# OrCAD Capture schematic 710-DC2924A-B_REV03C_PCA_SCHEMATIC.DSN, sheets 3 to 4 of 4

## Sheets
3 PAGE2: size Custom; title: DSP6713 SYSTEM; rev: V1.0; company: WITH DIGITAL POWER MANAGEMENT; note: 4 X 30A STEP-DOWN µMODULE SUPPLY WITH PSM
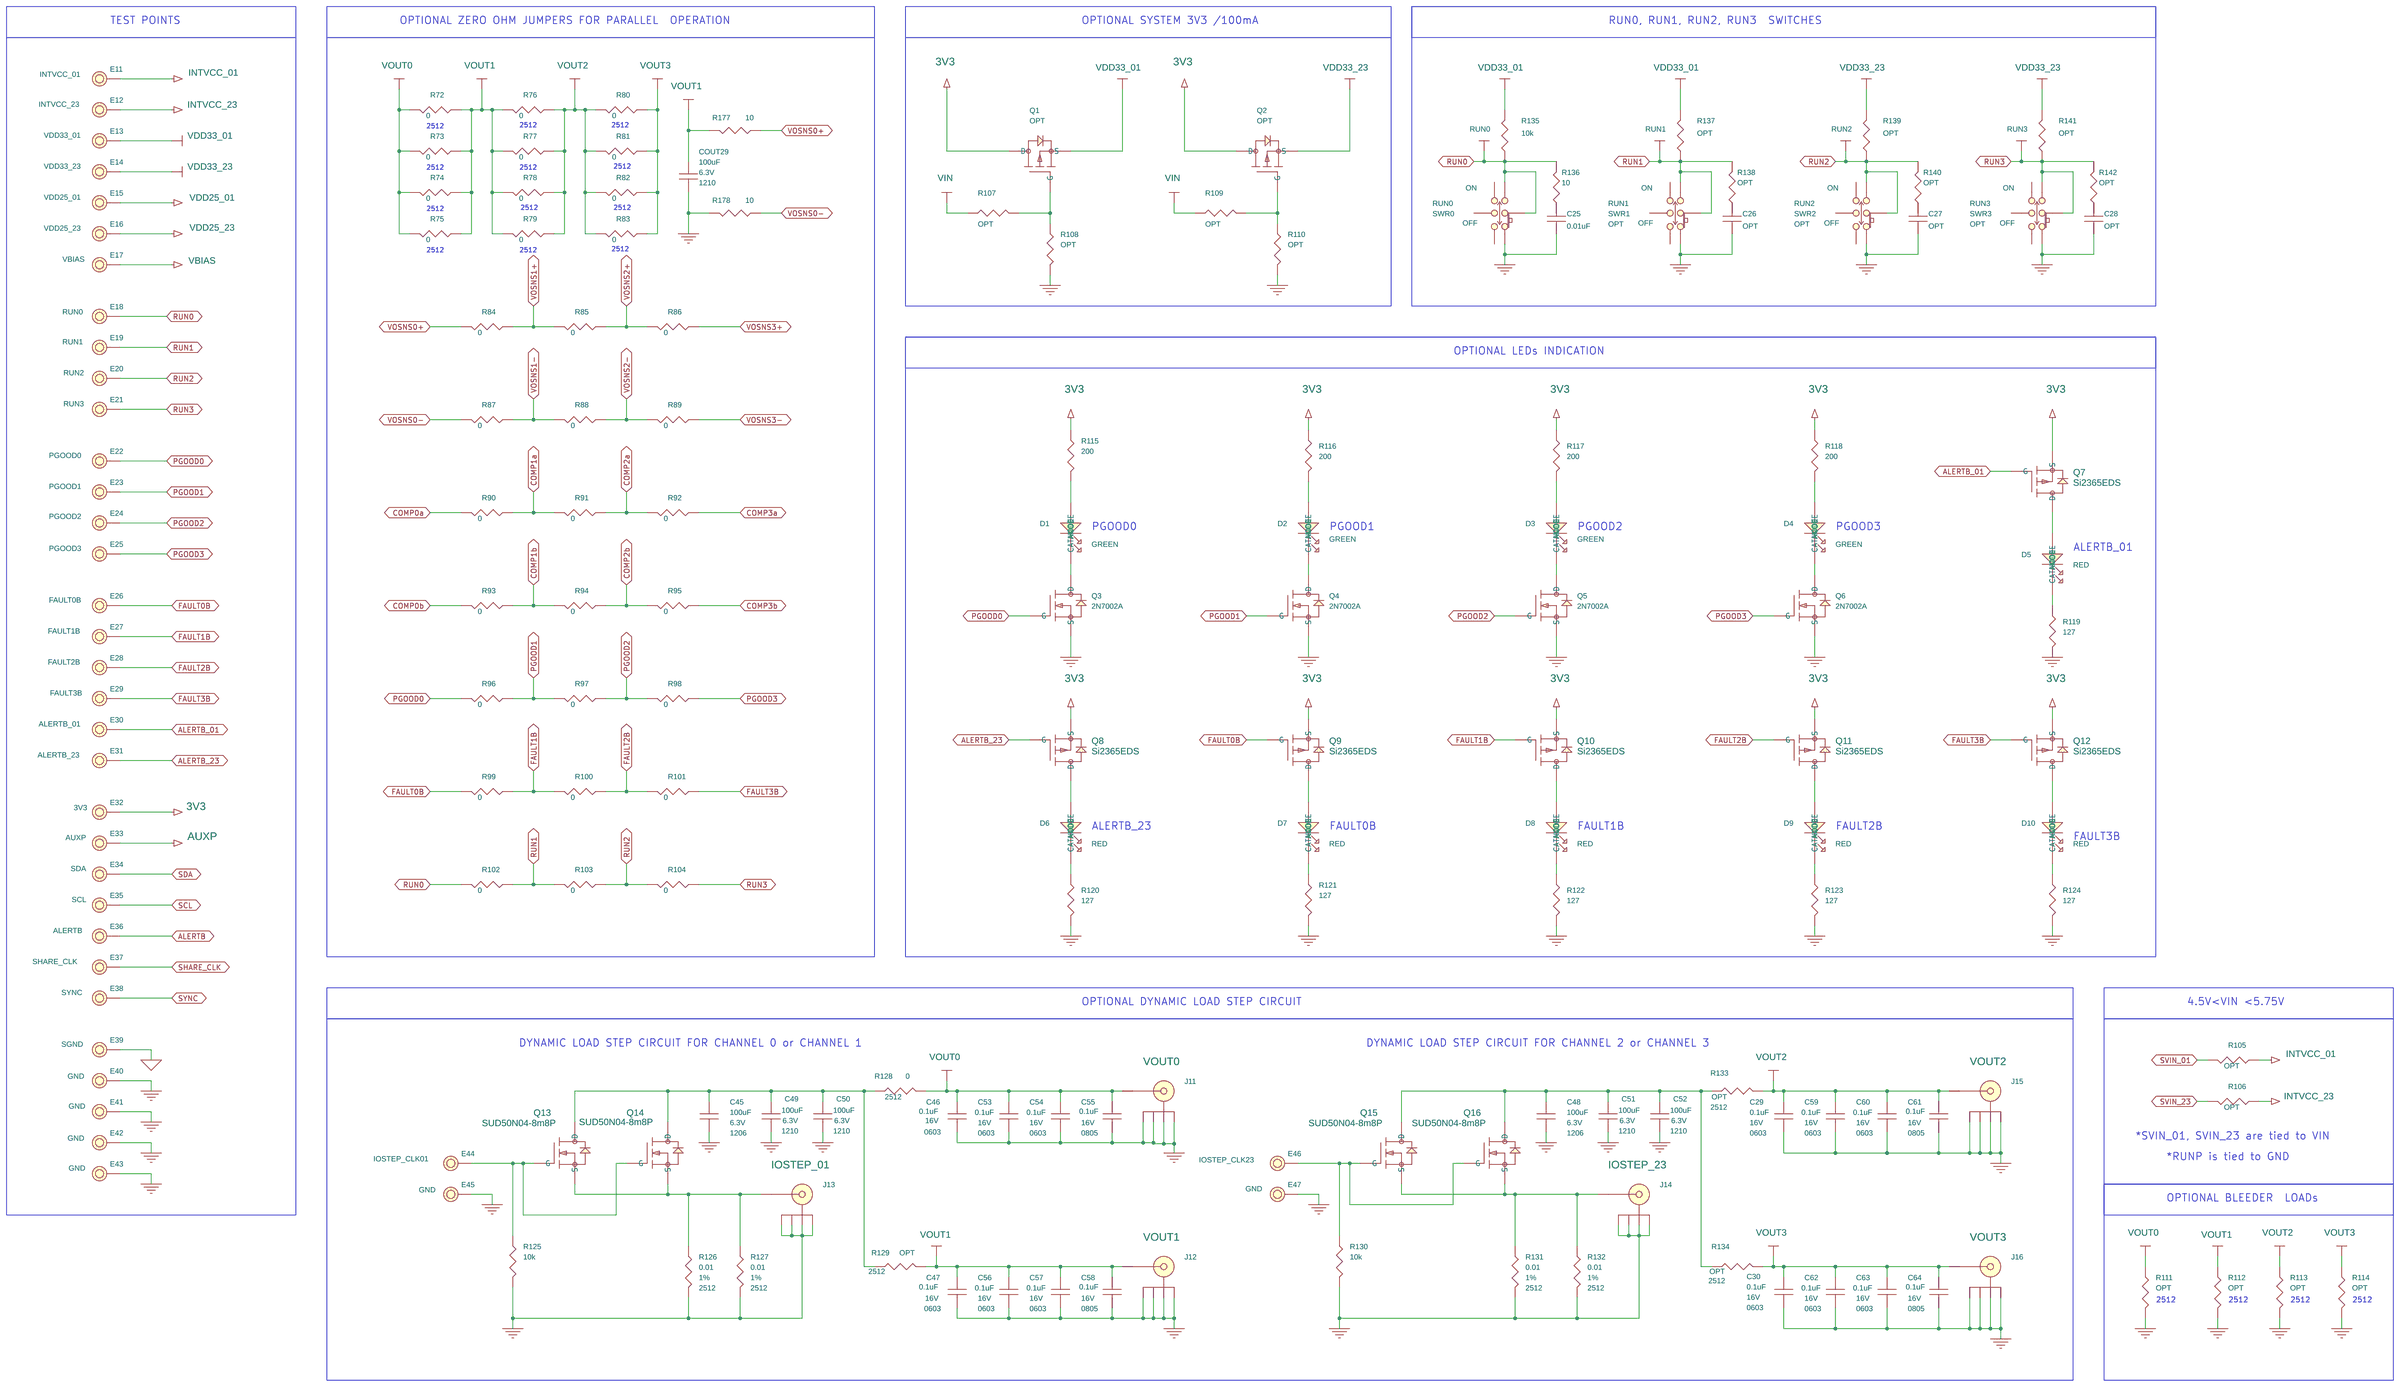
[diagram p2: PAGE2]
4 PAGE3: size Custom; title: DSP6713 SYSTEM; rev: V1.0; company: WITH DIGITAL POWER MANAGEMENT; note: 4 X 30A STEP-DOWN µMODULE SUPPLY WITH PSM
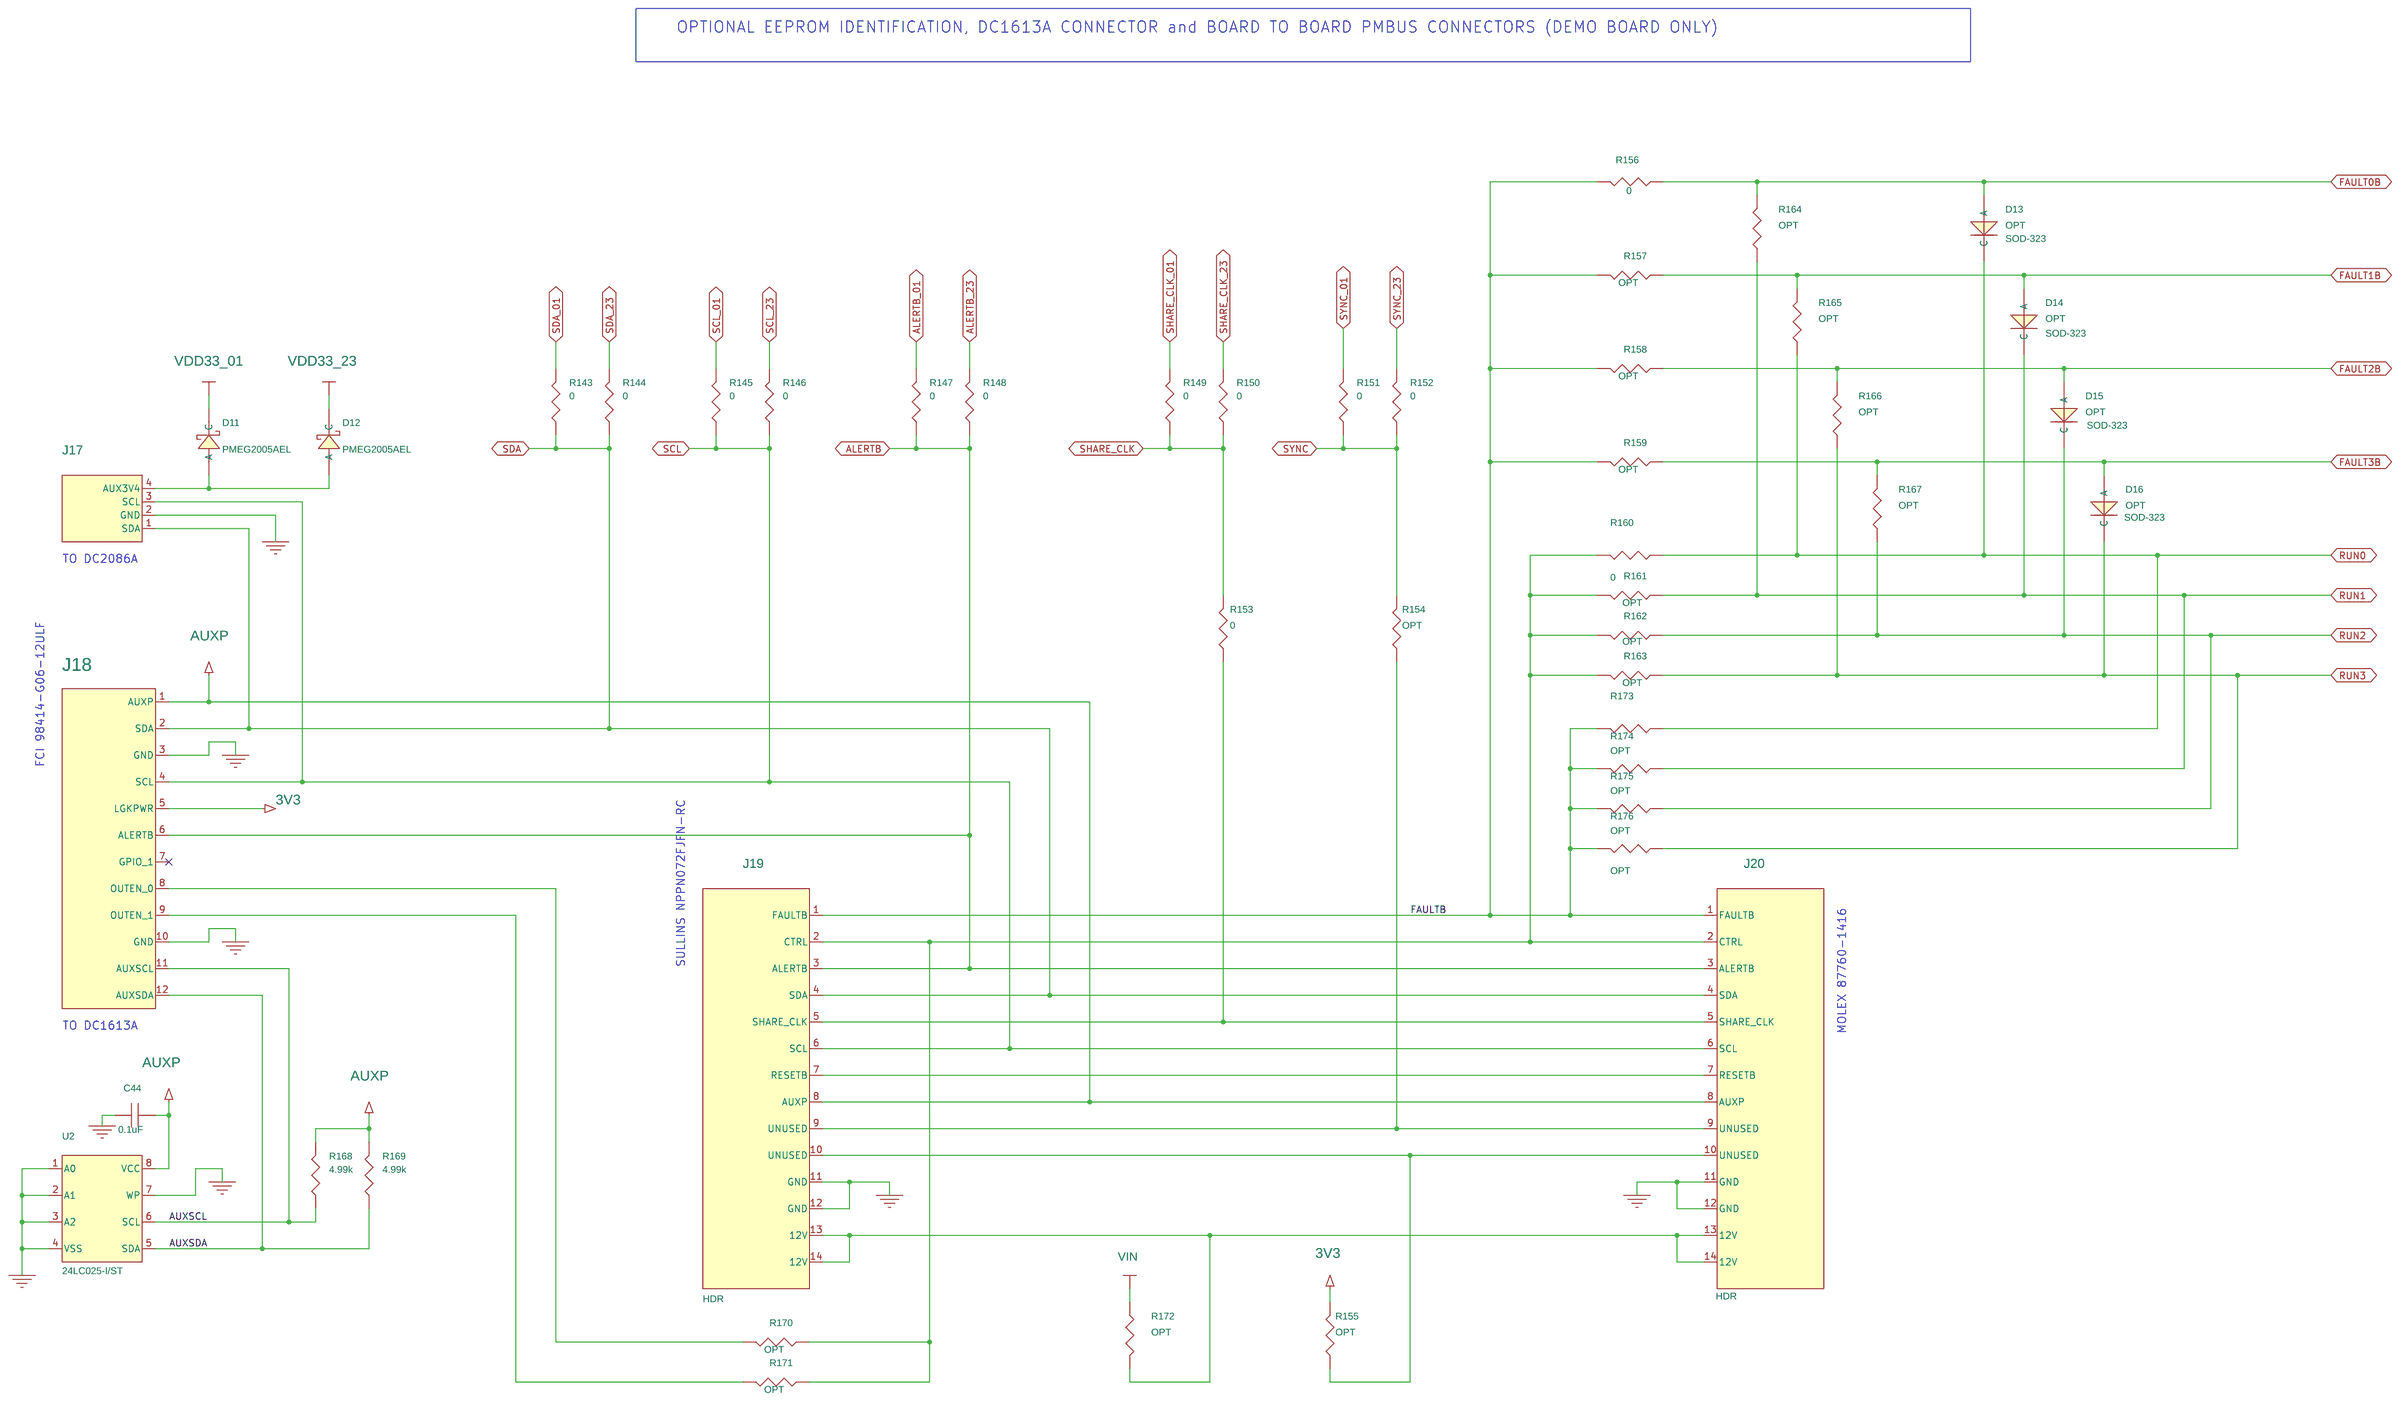
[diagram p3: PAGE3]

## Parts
sheet PAGE2
C25  0.01uF  [CC0603N]
C26  OPT  [CC0603N]
C27  OPT  [CC0603N]
C28  OPT  [CC0603N]
C29  0.1uF  [CC0603N]
C30  0.1uF  [CC0603N]
C45  100uF  [CC1206N]
C46  0.1uF  [CC0603N]
C47  0.1uF  [CC0603N]
C48  100uF  [CC1206N]
C49  100uF  [CC1210N]
C50  100uF  [CC1210N]
C51  100uF  [CC1210N]
C52  100uF  [CC1210N]
C53  0.1uF  [CC0603N]
C54  0.1uF  [CC0603N]
C55  0.1uF  [CC0805N]
C56  0.1uF  [CC0603N]
C57  0.1uF  [CC0603N]
C58  0.1uF  [CC0805N]
C59  0.1uF  [CC0603N]
C60  0.1uF  [CC0603N]
C61  0.1uF  [CC0805N]
C62  0.1uF  [CC0603N]
C63  0.1uF  [CC0603N]
C64  0.1uF  [CC0805N]
COUT29  100uF  [CC1210N]
D1  GREEN  [LED_0603]
D2  GREEN  [LED_0603]
D3  GREEN  [LED_0603]
D4  GREEN  [LED_0603]
D5  RED  [LED_0603]
D6  RED  [LED_0603]
D7  RED  [LED_0603]
D8  RED  [LED_0603]
D9  RED  [LED_0603]
D10  RED  [LED_0603]
E11  TEST POINT  [MILLMAX2501]
E12  TEST POINT  [MILLMAX2501]
E13  TEST POINT  [MILLMAX2501]
E14  TEST POINT  [MILLMAX2501]
E15  TEST POINT  [MILLMAX2501]
E16  TEST POINT  [MILLMAX2501]
E17  TEST POINT  [MILLMAX2501]
E18  TEST POINT  [MILLMAX2501]
E19  TEST POINT  [MILLMAX2501]
E20  TEST POINT  [MILLMAX2501]
E21  TEST POINT  [MILLMAX2501]
E22  TEST POINT  [MILLMAX2501]
E23  TEST POINT  [MILLMAX2501]
E24  TEST POINT  [MILLMAX2501]
E25  TEST POINT  [MILLMAX2501]
E26  TEST POINT  [MILLMAX2501]
E27  TEST POINT  [MILLMAX2501]
E28  TEST POINT  [MILLMAX2501]
E29  TEST POINT  [MILLMAX2501]
E30  TEST POINT  [MILLMAX2501]
E31  TEST POINT  [MILLMAX2501]
E32  TEST POINT  [MILLMAX2501]
E33  TEST POINT  [MILLMAX2501]
E34  TEST POINT  [MILLMAX2501]
E35  TEST POINT  [MILLMAX2501]
E36  TEST POINT  [MILLMAX2501]
E37  TEST POINT  [MILLMAX2501]
E38  TEST POINT  [MILLMAX2501]
E39  TEST POINT  [MILLMAX2501]
E40  TEST POINT  [MILLMAX2501]
E41  TEST POINT  [MILLMAX2501]
E42  TEST POINT  [MILLMAX2501]
E43  TEST POINT  [MILLMAX2501]
E44  TEST POINT  [MILLMAX2501]
E45  TEST POINT  [MILLMAX2501]
E46  TEST POINT  [MILLMAX2501]
E47  TEST POINT  [MILLMAX2501]
J11  RF,BNC  [CONNEX-112404]
J12  RF,BNC  [CONNEX-112404]
J13  RF,BNC  [CONNEX-112404]
J14  RF,BNC  [CONNEX-112404]
J15  RF,BNC  [CONNEX-112404]
J16  RF,BNC  [CONNEX-112404]
Q1  OPT  [SOT23-3N]
Q2  OPT  [SOT23-3N]
Q3  2N7002A  [SOT23-3N]
Q4  2N7002A  [SOT23-3N]
Q5  2N7002A  [SOT23-3N]
Q6  2N7002A  [SOT23-3N]
Q7  Si2365EDS  [SOT23-3N]
Q8  Si2365EDS  [SOT23-3N]
Q9  Si2365EDS  [SOT23-3N]
Q10  Si2365EDS  [SOT23-3N]
Q11  Si2365EDS  [SOT23-3N]
Q12  Si2365EDS  [SOT23-3N]
Q13  SUD50N04-8m8P  [TO-252-3N]
Q14  SUD50N04-8m8P  [TO-252-3N]
Q15  SUD50N04-8m8P  [TO-252-3N]
Q16  SUD50N04-8m8P  [TO-252-3N]
R72  0  [VISHAY-WSL_9-2512]
R73  0  [VISHAY-WSL_9-2512]
R74  0  [VISHAY-WSL_9-2512]
R75  0  [VISHAY-WSL_9-2512]
R76  0  [VISHAY-WSL_9-2512]
R77  0  [VISHAY-WSL_9-2512]
R78  0  [VISHAY-WSL_9-2512]
R79  0  [VISHAY-WSL_9-2512]
R80  0  [VISHAY-WSL_9-2512]
R81  0  [VISHAY-WSL_9-2512]
R82  0  [VISHAY-WSL_9-2512]
R83  0  [VISHAY-WSL_9-2512]
R84  0  [CR0603N]
R85  0  [CR0603N]
R86  0  [CR0603N]
R87  0  [CR0603N]
R88  0  [CR0603N]
R89  0  [CR0603N]
R90  0  [CR0603N]
R91  0  [CR0603N]
R92  0  [CR0603N]
R93  0  [CR0603N]
R94  0  [CR0603N]
R95  0  [CR0603N]
R96  0  [CR0603N]
R97  0  [CR0603N]
R98  0  [CR0603N]
R99  0  [CR0603N]
R100  0  [CR0603N]
R101  0  [CR0603N]
R102  0  [CR0603N]
R103  0  [CR0603N]
R104  0  [CR0603N]
R105  OPT  [CR0603N]
R106  OPT  [CR0603N]
R107  OPT  [CR0603N]
R108  OPT  [CR0603N]
R109  OPT  [CR0603N]
R110  OPT  [CR0603N]
R111  OPT  [CR2512N]
R112  OPT  [CR2512N]
R113  OPT  [CR2512N]
R114  OPT  [CR2512N]
R115  200  [CR0603N]
R116  200  [CR0603N]
R117  200  [CR0603N]
R118  200  [CR0603N]
R119  127  [CR0603N]
R120  127  [CR0603N]
R121  127  [CR0603N]
R122  127  [CR0603N]
R123  127  [CR0603N]
R124  127  [CR0603N]
R125  10k  [CR0603N]
R126  0.01  [PANASONIC-ERJM1WS]
R127  0.01  [PANASONIC-ERJM1WS]
R128  0  [VISHAY-WSL_9-2512]
R129  OPT  [CR2512N]
R130  10k  [CR0603N]
R131  0.01  [PANASONIC-ERJM1WS]
R132  0.01  [PANASONIC-ERJM1WS]
R133  OPT  [CR2512N]
R134  OPT  [CR2512N]
R135  10k  [CR0603N]
R136  10  [CR0603N]
R137  OPT  [CR0603N]
R138  OPT  [CR0603N]
R139  OPT  [CR0603N]
R140  OPT  [CR0603N]
R141  OPT  [CR0603N]
R142  OPT  [CR0603N]
R177  10  [CR0603N]
R178  10  [CR0603N]
SWR0  DPDT  [CK-JS202011CQN]
SWR1  OPT  [CK-JS202011CQN]
SWR2  OPT  [CK-JS202011CQN]
SWR3  OPT  [CK-JS202011CQN]
sheet PAGE3
C44  0.1uF  [CC0603N]
D11  PMEG2005AEL  [SOD-882N]
D12  PMEG2005AEL  [SOD-882N]
D13  OPT  [SOD-323N]
D14  OPT  [SOD-323N]
D15  OPT  [SOD-323N]
D16  OPT  [SOD-323N]
J17  HDR,SHROUDED  [HIROSE-DF3A-4P-2DSA]
J18  HDR,SHROUDED  [HD2X6-079-MOLEX]
J19  HDR  [SULLINS-NPPN072FJFN-RC]
J20  HDR  [MOLEX-0877601416]
R143  0  [CR0603N]
R144  0  [CR0603N]
R145  0  [CR0603N]
R146  0  [CR0603N]
R147  0  [CR0603N]
R148  0  [CR0603N]
R149  0  [CR0603N]
R150  0  [CR0603N]
R151  0  [CR0603N]
R152  0  [CR0603N]
R153  0  [CR0603N]
R154  OPT  [CR0603N]
R155  OPT  [CR0603N]
R156  0  [CR0603N]
R157  OPT  [CR0603N]
R158  OPT  [CR0603N]
R159  OPT  [CR0603N]
R160  0  [CR0603N]
R161  OPT  [CR0603N]
R162  OPT  [CR0603N]
R163  OPT  [CR0603N]
R164  OPT  [CR0603N]
R165  OPT  [CR0603N]
R166  OPT  [CR0603N]
R167  OPT  [CR0603N]
R168  4.99k  [CR0603N]
R169  4.99k  [CR0603N]
R170  OPT  [CR0603N]
R171  OPT  [CR0603N]
R172  OPT  [CR0603N]
R173  OPT  [CR0603N]
R174  OPT  [CR0603N]
R175  OPT  [CR0603N]
R176  OPT  [CR0603N]
U2  24LC025-I/ST  [MO-153AA_N]

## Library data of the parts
C25 = CAP: CAP.,0.01uF,X7R,50V,10%,0603; CLASS: DISCRETE; Dielectric Type: X7R; FPLIST: CC0603N,CC0603L,CC0603M; Inventory Qty: 28483; Manufacturer: AVX; Manufacturer PN: 06035C103KAT2A; PART_NUMBER: 150-0002; Package Size: 0603; Rated Voltage: 50V; Tolerance: 10%
C26-C28 = CAP: CAP., OPTION, 0603; CLASS: DISCRETE; FPLIST: CC0603N,CC0603L,CC0603M; PART_NUMBER: 150-3038; Package Size: 0603; Package Type: SMD
C29 C30 C44 C46 C47 C53 C54 C56 C57 C59 C60 C62 C63 = CAP: CAP.,0.1uF,X7R,16V,10%,0603,FLEXITERM; CLASS: DISCRETE; Dielectric Type: X7R; FPLIST: CC0603N,CC0603L,CC0603M; Inventory Qty: 23544; Manufacturer: AVX; Manufacturer PN: 0603YC104KAZ2A; PART_NUMBER: 150-0165; Package Size: 0603; Rated Voltage: 16V; Tolerance: 10%
C45 C48 = CAP: CAP.,100uF,X5R,6.3V,10%,1206; CLASS: DISCRETE; Dielectric Type: X5R; FPLIST: CC1206N,CC1206L,CC1206M; Inventory Qty: 5866; Manufacturer: MURATA; Manufacturer PN: GRM31CR60J107KE39L; PART_NUMBER: 150-2327; Package Size: 1206; Rated Voltage: 6.3V; Tolerance: 10%
C49-C52 COUT29 = CAP: CAP.,100uF,X5R,6.3V,20%,1210; CLASS: DISCRETE; Dielectric Type: X5R; FPLIST: CC1210N,CC1210L,CC1210M; Inventory Qty: 50440; Manufacturer: AVX; Manufacturer PN: 12106D107MAT2A; PART_NUMBER: 150-3008; Package Size: 1210; Rated Voltage: 6.3V; Tolerance: 20%
C55 C58 C61 C64 = CAP: CAP.,0.1uF,X7R,16V,10%,0805; CLASS: DISCRETE; Dielectric Type: X7R; FPLIST: CC0805N,CC0805L,CC0805M; Inventory Qty: 17724; Manufacturer: KEMET; Manufacturer PN: C0805C104K4RACTU; PART_NUMBER: 150-0090; Package Size: 0805; Package Type: SMD; Rated Voltage: 16V; Tolerance: 10%
D1-D4 = LED: LED,GREEN,WATER CLEAR,0603; CLASS: DISCRETE; Inventory Qty: 10859; Manufacturer: WURTH ELEKTRONIK; Manufacturer PN: 150060GS75000; PART_NUMBER: 270-0057; Package Type: 0603
D5-D10 = LED: LED,RED,WATER CLEAR,0603; CLASS: DISCRETE; Inventory Qty: 17176; Label: GREEN; Manufacturer: WURTH ELEKTRONIK; Manufacturer PN: 150060RS75000; PART_NUMBER: 270-0071; Package Type: 0603
E11 = TESTPOINT_.219_MILL-MAX_2501: TEST POINT,TURRET,0.094" MTG. HOLE,PCB 0.062" THK; 9th Part Field: INTVCC_01; CLASS: IO; Inventory Qty: 823526; Manufacturer: MILL-MAX; Manufacturer PN: 2501-2-00-80-00-00-07-0; PART_NUMBER: 260-0003
E12 = TESTPOINT_.219_MILL-MAX_2501: TEST POINT,TURRET,0.094" MTG. HOLE,PCB 0.062" THK; 9th Part Field: INTVCC_23; CLASS: IO; Inventory Qty: 823526; Manufacturer: MILL-MAX; Manufacturer PN: 2501-2-00-80-00-00-07-0; PART_NUMBER: 260-0003
E13 = TESTPOINT_.219_MILL-MAX_2501: TEST POINT,TURRET,0.094" MTG. HOLE,PCB 0.062" THK; 9th Part Field: VDD33_01; CLASS: IO; Inventory Qty: 823526; Manufacturer: MILL-MAX; Manufacturer PN: 2501-2-00-80-00-00-07-0; PART_NUMBER: 260-0003
E14 = TESTPOINT_.219_MILL-MAX_2501: TEST POINT,TURRET,0.094" MTG. HOLE,PCB 0.062" THK; 9th Part Field: VDD33_23; CLASS: IO; Inventory Qty: 823526; Manufacturer: MILL-MAX; Manufacturer PN: 2501-2-00-80-00-00-07-0; PART_NUMBER: 260-0003
E15 = TESTPOINT_.219_MILL-MAX_2501: TEST POINT,TURRET,0.094" MTG. HOLE,PCB 0.062" THK; 9th Part Field: VDD25_01; CLASS: IO; Inventory Qty: 823526; Manufacturer: MILL-MAX; Manufacturer PN: 2501-2-00-80-00-00-07-0; PART_NUMBER: 260-0003
E16 = TESTPOINT_.219_MILL-MAX_2501: TEST POINT,TURRET,0.094" MTG. HOLE,PCB 0.062" THK; 9th Part Field: VDD25_23; CLASS: IO; Inventory Qty: 823526; Manufacturer: MILL-MAX; Manufacturer PN: 2501-2-00-80-00-00-07-0; PART_NUMBER: 260-0003
E17 = TESTPOINT_.219_MILL-MAX_2501: TEST POINT,TURRET,0.094" MTG. HOLE,PCB 0.062" THK; 9th Part Field: VBIAS; CLASS: IO; Inventory Qty: 823526; Manufacturer: MILL-MAX; Manufacturer PN: 2501-2-00-80-00-00-07-0; PART_NUMBER: 260-0003
E18 = TESTPOINT_.219_MILL-MAX_2501: TEST POINT,TURRET,0.094" MTG. HOLE,PCB 0.062" THK; 9th Part Field: RUN0; CLASS: IO; Inventory Qty: 823526; Manufacturer: MILL-MAX; Manufacturer PN: 2501-2-00-80-00-00-07-0; PART_NUMBER: 260-0003
E19 = TESTPOINT_.219_MILL-MAX_2501: TEST POINT,TURRET,0.094" MTG. HOLE,PCB 0.062" THK; 9th Part Field: RUN1; CLASS: IO; Inventory Qty: 823526; Manufacturer: MILL-MAX; Manufacturer PN: 2501-2-00-80-00-00-07-0; PART_NUMBER: 260-0003
E20 = TESTPOINT_.219_MILL-MAX_2501: TEST POINT,TURRET,0.094" MTG. HOLE,PCB 0.062" THK; 9th Part Field: RUN2; CLASS: IO; Inventory Qty: 823526; Manufacturer: MILL-MAX; Manufacturer PN: 2501-2-00-80-00-00-07-0; PART_NUMBER: 260-0003
E21 = TESTPOINT_.219_MILL-MAX_2501: TEST POINT,TURRET,0.094" MTG. HOLE,PCB 0.062" THK; 9th Part Field: RUN3; CLASS: IO; Inventory Qty: 823526; Manufacturer: MILL-MAX; Manufacturer PN: 2501-2-00-80-00-00-07-0; PART_NUMBER: 260-0003
E22 = TESTPOINT_.219_MILL-MAX_2501: TEST POINT,TURRET,0.094" MTG. HOLE,PCB 0.062" THK; 9th Part Field: PGOOD0; CLASS: IO; Inventory Qty: 823526; Manufacturer: MILL-MAX; Manufacturer PN: 2501-2-00-80-00-00-07-0; PART_NUMBER: 260-0003
E23 = TESTPOINT_.219_MILL-MAX_2501: TEST POINT,TURRET,0.094" MTG. HOLE,PCB 0.062" THK; 9th Part Field: PGOOD1; CLASS: IO; Inventory Qty: 823526; Manufacturer: MILL-MAX; Manufacturer PN: 2501-2-00-80-00-00-07-0; PART_NUMBER: 260-0003
E24 = TESTPOINT_.219_MILL-MAX_2501: TEST POINT,TURRET,0.094" MTG. HOLE,PCB 0.062" THK; 9th Part Field: PGOOD2; CLASS: IO; Inventory Qty: 823526; Manufacturer: MILL-MAX; Manufacturer PN: 2501-2-00-80-00-00-07-0; PART_NUMBER: 260-0003
E25 = TESTPOINT_.219_MILL-MAX_2501: TEST POINT,TURRET,0.094" MTG. HOLE,PCB 0.062" THK; 9th Part Field: PGOOD3; CLASS: IO; Inventory Qty: 823526; Manufacturer: MILL-MAX; Manufacturer PN: 2501-2-00-80-00-00-07-0; PART_NUMBER: 260-0003
E26 = TESTPOINT_.219_MILL-MAX_2501: TEST POINT,TURRET,0.094" MTG. HOLE,PCB 0.062" THK; 9th Part Field: FAULT0B; CLASS: IO; Inventory Qty: 823526; Manufacturer: MILL-MAX; Manufacturer PN: 2501-2-00-80-00-00-07-0; PART_NUMBER: 260-0003
E27 = TESTPOINT_.219_MILL-MAX_2501: TEST POINT,TURRET,0.094" MTG. HOLE,PCB 0.062" THK; 9th Part Field: FAULT1B; CLASS: IO; Inventory Qty: 823526; Manufacturer: MILL-MAX; Manufacturer PN: 2501-2-00-80-00-00-07-0; PART_NUMBER: 260-0003
E28 = TESTPOINT_.219_MILL-MAX_2501: TEST POINT,TURRET,0.094" MTG. HOLE,PCB 0.062" THK; 9th Part Field: FAULT2B; CLASS: IO; Inventory Qty: 823526; Manufacturer: MILL-MAX; Manufacturer PN: 2501-2-00-80-00-00-07-0; PART_NUMBER: 260-0003
E29 = TESTPOINT_.219_MILL-MAX_2501: TEST POINT,TURRET,0.094" MTG. HOLE,PCB 0.062" THK; 9th Part Field: FAULT3B; CLASS: IO; Inventory Qty: 823526; Manufacturer: MILL-MAX; Manufacturer PN: 2501-2-00-80-00-00-07-0; PART_NUMBER: 260-0003
E30 = TESTPOINT_.219_MILL-MAX_2501: TEST POINT,TURRET,0.094" MTG. HOLE,PCB 0.062" THK; 9th Part Field: ALERTB_01; CLASS: IO; Inventory Qty: 823526; Manufacturer: MILL-MAX; Manufacturer PN: 2501-2-00-80-00-00-07-0; PART_NUMBER: 260-0003
E31 = TESTPOINT_.219_MILL-MAX_2501: TEST POINT,TURRET,0.094" MTG. HOLE,PCB 0.062" THK; 9th Part Field: ALERTB_23; CLASS: IO; Inventory Qty: 823526; Manufacturer: MILL-MAX; Manufacturer PN: 2501-2-00-80-00-00-07-0; PART_NUMBER: 260-0003
E32 = TESTPOINT_.219_MILL-MAX_2501: TEST POINT,TURRET,0.094" MTG. HOLE,PCB 0.062" THK; 9th Part Field: 3V3; CLASS: IO; Inventory Qty: 823526; Manufacturer: MILL-MAX; Manufacturer PN: 2501-2-00-80-00-00-07-0; PART_NUMBER: 260-0003
E33 = TESTPOINT_.219_MILL-MAX_2501: TEST POINT,TURRET,0.094" MTG. HOLE,PCB 0.062" THK; 9th Part Field: AUXP; CLASS: IO; Inventory Qty: 823526; Manufacturer: MILL-MAX; Manufacturer PN: 2501-2-00-80-00-00-07-0; PART_NUMBER: 260-0003
E34 = TESTPOINT_.219_MILL-MAX_2501: TEST POINT,TURRET,0.094" MTG. HOLE,PCB 0.062" THK; 9th Part Field: SDA; CLASS: IO; Inventory Qty: 823526; Manufacturer: MILL-MAX; Manufacturer PN: 2501-2-00-80-00-00-07-0; PART_NUMBER: 260-0003
E35 = TESTPOINT_.219_MILL-MAX_2501: TEST POINT,TURRET,0.094" MTG. HOLE,PCB 0.062" THK; 9th Part Field: SCL; CLASS: IO; Inventory Qty: 823526; Manufacturer: MILL-MAX; Manufacturer PN: 2501-2-00-80-00-00-07-0; PART_NUMBER: 260-0003
E36 = TESTPOINT_.219_MILL-MAX_2501: TEST POINT,TURRET,0.094" MTG. HOLE,PCB 0.062" THK; 9th Part Field: ALERTB; CLASS: IO; Inventory Qty: 823526; Manufacturer: MILL-MAX; Manufacturer PN: 2501-2-00-80-00-00-07-0; PART_NUMBER: 260-0003
E37 = TESTPOINT_.219_MILL-MAX_2501: TEST POINT,TURRET,0.094" MTG. HOLE,PCB 0.062" THK; 9th Part Field: SHARE_CLK; CLASS: IO; Inventory Qty: 823526; Manufacturer: MILL-MAX; Manufacturer PN: 2501-2-00-80-00-00-07-0; PART_NUMBER: 260-0003
E38 = TESTPOINT_.219_MILL-MAX_2501: TEST POINT,TURRET,0.094" MTG. HOLE,PCB 0.062" THK; 9th Part Field: SYNC; CLASS: IO; Inventory Qty: 823526; Manufacturer: MILL-MAX; Manufacturer PN: 2501-2-00-80-00-00-07-0; PART_NUMBER: 260-0003
E39 = TESTPOINT_.219_MILL-MAX_2501: TEST POINT,TURRET,0.094" MTG. HOLE,PCB 0.062" THK; 9th Part Field: SGND; CLASS: IO; Inventory Qty: 823526; Manufacturer: MILL-MAX; Manufacturer PN: 2501-2-00-80-00-00-07-0; PART_NUMBER: 260-0003
E40-E43 E45 E47 = TESTPOINT_.219_MILL-MAX_2501: TEST POINT,TURRET,0.094" MTG. HOLE,PCB 0.062" THK; 9th Part Field: GND; CLASS: IO; Inventory Qty: 823526; Manufacturer: MILL-MAX; Manufacturer PN: 2501-2-00-80-00-00-07-0; PART_NUMBER: 260-0003
E44 = TESTPOINT_.219_MILL-MAX_2501: TEST POINT,TURRET,0.094" MTG. HOLE,PCB 0.062" THK; 9th Part Field: IOSTEP_CLK01; CLASS: IO; Inventory Qty: 823526; Manufacturer: MILL-MAX; Manufacturer PN: 2501-2-00-80-00-00-07-0; PART_NUMBER: 260-0003
E46 = TESTPOINT_.219_MILL-MAX_2501: TEST POINT,TURRET,0.094" MTG. HOLE,PCB 0.062" THK; 9th Part Field: IOSTEP_CLK23; CLASS: IO; Inventory Qty: 823526; Manufacturer: MILL-MAX; Manufacturer PN: 2501-2-00-80-00-00-07-0; PART_NUMBER: 260-0003
J11 = BNC_50_OHM_112404_C: CONN.,RF,BNC,RCPT,JACK,5-PIN,ST,THT,50 OHMS; CLASS: IO; Inventory Qty: 80023; Manufacturer: AMPHENOL RF; Manufacturer PN: 112404; PART_FIELD_01: VOUT0; PART_NUMBER: 250-0427
J12 = BNC_50_OHM_112404_C: CONN.,RF,BNC,RCPT,JACK,5-PIN,ST,THT,50 OHMS; CLASS: IO; Inventory Qty: 80023; Manufacturer: AMPHENOL RF; Manufacturer PN: 112404; PART_FIELD_01: VOUT1; PART_NUMBER: 250-0427
J13 = BNC_50_OHM_112404_C: CONN.,RF,BNC,RCPT,JACK,5-PIN,ST,THT,50 OHMS; CLASS: IO; Inventory Qty: 80023; Manufacturer: AMPHENOL RF; Manufacturer PN: 112404; PART_FIELD_01: IOSTEP_01; PART_NUMBER: 250-0427
J14 = BNC_50_OHM_112404_C: CONN.,RF,BNC,RCPT,JACK,5-PIN,ST,THT,50 OHMS; CLASS: IO; Inventory Qty: 80023; Manufacturer: AMPHENOL RF; Manufacturer PN: 112404; PART_FIELD_01: IOSTEP_23; PART_NUMBER: 250-0427
J15 = BNC_50_OHM_112404_C: CONN.,RF,BNC,RCPT,JACK,5-PIN,ST,THT,50 OHMS; CLASS: IO; Inventory Qty: 80023; Manufacturer: AMPHENOL RF; Manufacturer PN: 112404; PART_FIELD_01: VOUT2; PART_NUMBER: 250-0427
J16 = BNC_50_OHM_112404_C: CONN.,RF,BNC,RCPT,JACK,5-PIN,ST,THT,50 OHMS; CLASS: IO; Inventory Qty: 80023; Manufacturer: AMPHENOL RF; Manufacturer PN: 112404; PART_FIELD_01: VOUT3; PART_NUMBER: 250-0427
Q1 Q2 = 3P_P-CH_TYPE1A: XSTR., OPTION, MOSFET, P-CH, SOT-23; CLASS: DISCRETE; FPLIST: SOT23-3N,SOT23-3L,SOT23-3M; PART_NUMBER: 240-0336; Package Type: SOT-23
Q3-Q6 = 3P_N-CH_TYPE1A: XSTR.,MOSFET,N-CH,60V,220mA,SOT23-3,AEC-Q101; CLASS: DISCRETE; FPLIST: SOT23-3N,SOT23-3L,SOT23-3M; Inventory Qty: 9660; Manufacturer: DIODES INC.; Manufacturer PN: 2N7002A-13; PART_NUMBER: 240-0059; Package Type: SOT23-3; Rated Voltage: 60V
Q7-Q12 = 3P_P-CH_TYPE1A: XSTR.,MOSFET,P-CH,20V,5.9A,SOT-23-3 (TO-236-3); CLASS: DISCRETE; Inventory Qty: 18908; Manufacturer: VISHAY; Manufacturer PN: Si2365EDS-T1-GE3; PART_NUMBER: 240-0119; Package Size: SOT-23; Package Type: SOT-23-3 (TO-236-3); Rated Voltage: 20V
Q13-Q16 = 3P_N-CH_TYPE2A: XSTR.,MOSFET,N-CH,40V,14A,DPAK (TO-252); CLASS: DISCRETE; Inventory Qty: 44191; Manufacturer: VISHAY; Manufacturer PN: SUD50N04-8M8P-4GE3; PART_NUMBER: 240-0021; Package Type: DPAK (TO-252); Rated Voltage: 40V
R72-R83 R128 = RES: RES.,0 OHM,1W,2512,SENSE,COPPER; CLASS: DISCRETE; Inventory Qty: 7479; Manufacturer: VISHAY; Manufacturer PN: WSL251200000ZEA9; PART_NUMBER: 100-0588; Package Size: 2512; Rated Power: 1W; Temperature Coefficient: 3900ppm
R84-R104 R143-R153 R156 R160 = RES: RES.,0 OHM,1/10W,0603,AEC-Q200; CLASS: DISCRETE; FPLIST: CR0603N,CR0603L,CR0603M; Inventory Qty: 700742; Manufacturer: VISHAY; Manufacturer PN: CRCW06030000Z0EA; PART_NUMBER: 100-0009; Package Size: 0603; Rated Power: 1/10W
R105-R110 R137-R142 R154 R155 R157-R159 R161-R167 R170-R176 = RES: RES., OPTION, 0603; CLASS: DISCRETE; FPLIST: CR0603N,CR0603L,CR0603M; PART_NUMBER: 100-2374; Package Size: 0603
R111-R114 = RES: RES., OPTION, 2512; CLASS: DISCRETE; FPLIST: CR2512N,CR2512L,CR2512M,USER_ASSIGNED; PART_NUMBER: 100-2376; Package Size: 2512
R115-R118 = RES: RES.,200 OHMS,1%,1/10W,0603; CLASS: DISCRETE; FPLIST: CR0603N,CR0603L,CR0603M; Inventory Qty: 36974; Label: OPT 0; Manufacturer: VISHAY; Manufacturer PN: CRCW0603200RFKEA; PART_NUMBER: 100-0130; Package Size: 0603; Rated Power: 1/10W; Temperature Coefficient: 100ppm; Tolerance: 1%
R119-R124 = RES: RES.,127 OHMS,1%,1/10W,0603,AEC-Q200; CLASS: DISCRETE; FPLIST: CR0603N,CR0603L,CR0603M; Inventory Qty: 79992; Label: OPT 0; Manufacturer: NIC; Manufacturer PN: NRC06F1270TRF; PART_NUMBER: 100-0054; Package Size: 0603; Rated Power: 1/10W; Temperature Coefficient: 100ppm/C; Tolerance: 1%
R125 R130 R135 = RES: RES.,10k OHMS,1%,1/10W,0603,AEC-Q200; CLASS: DISCRETE; FPLIST: CR0603N,CR0603L,CR0603M; Inventory Qty: 194448; Manufacturer: VISHAY; Manufacturer PN: CRCW060310K0FKEA; PART_NUMBER: 100-2012; Package Size: 0603; Rated Power: 1/10W; Temperature Coefficient: +/-100ppm/C; Tolerance: 1%
R126 R127 R131 R132 = RES: RES.,0.01 OHM,1%,1W,2512,METAL,SENSE; CLASS: DISCRETE; FPLIST: CR2512N,CR2512L,CR2512M; Inventory Qty: 22067; Manufacturer: PANASONIC; Manufacturer PN: ERJM1WSF10MU; PART_NUMBER: 100-0248; Package Size: 2512; Rated Power: 1W; Temperature Coefficient: 100ppm/C; Tolerance: 1%
R129 R134 = RES: RES., OPTION, 2512; BOM Notes: R100,R101= 1/2W 1%; CLASS: DISCRETE; FPLIST: CR2512N,CR2512L,CR2512M,RSENSE-2512-4PIN,RSENSE-2512-6PIN; PART_FIELD_01: 1W 1%; PART_NUMBER: 100-2376; Package Size: 2512
R133 = RES: RES., OPTION, 2512; CLASS: DISCRETE; FPLIST: CR2512N,CR2512L,CR2512M,RSENSE-2512-4PIN,RSENSE-2512-6PIN; PART_NUMBER: 100-2376; Package Size: 2512
R136 R177 R178 = RES: RES.,10 OHMS,1%,1/10W,0603; CLASS: DISCRETE; FPLIST: CR0603N,CR0603L,CR0603M; Inventory Qty: 152750; Manufacturer: VISHAY; Manufacturer PN: CRCW060310R0FKEA; PART_NUMBER: 100-2306; Package Size: 0603; Rated Power: 1/10W; Temperature Coefficient: 100ppm/C; Tolerance: 1%
SWR0 = SW-DPDT-JS202011CQN_ALT1: SWITCH,SLIDE,DPDT,0.3A,6VDC,PTH; CLASS: DISCRETE; Inventory Qty: 32171; Manufacturer: C&K; Manufacturer PN: JS202011CQN; PART_FIELD_01: ON; PART_FIELD_02: OFF; PART_FIELD_03: RUN0; PART_NUMBER: 430-0039
SWR1 = SW-DPDT-JS202011CQN_ALT1: SWITCH,SLIDE,DPDT,0.3A,6VDC,PTH; CLASS: DISCRETE; Inventory Qty: 32171; Manufacturer: C&K; Manufacturer PN: JS202011CQN; PART_FIELD_01: ON; PART_FIELD_02: OFF; PART_FIELD_03: RUN1; PART_NUMBER: 430-0039
SWR2 = SW-DPDT-JS202011CQN_ALT1: SWITCH,SLIDE,DPDT,0.3A,6VDC,PTH; CLASS: DISCRETE; Inventory Qty: 32171; Manufacturer: C&K; Manufacturer PN: JS202011CQN; PART_FIELD_01: ON; PART_FIELD_02: OFF; PART_FIELD_03: RUN2; PART_NUMBER: 430-0039
SWR3 = SW-DPDT-JS202011CQN_ALT1: SWITCH,SLIDE,DPDT,0.3A,6VDC,PTH; CLASS: DISCRETE; Inventory Qty: 32171; Manufacturer: C&K; Manufacturer PN: JS202011CQN; PART_FIELD_01: ON; PART_FIELD_02: OFF; PART_FIELD_03: RUN3; PART_NUMBER: 430-0039
D11 D12 = DIODE_SCHOTTKY_A: DIODE,SCHOTTKY,20V,0.5A,SOD-882,LEADLESS; CLASS: DISCRETE; Inventory Qty: 13051; Manufacturer: NEXPERIA; Manufacturer PN: PMEG2005AEL,315; Max Forward Current or Rated Power: 0.5A; PART_NUMBER: 210-0105; Package Type: SOD-882; Rated Voltage: 20V; Rated Voltage or Zener Voltage: 20V
D13-D16 = DIODE_A: DIODE, OPTION, SOD-323; CLASS: DISCRETE; FPLIST: SOD-323N,SOD-323L,SOD-323M; PART_NUMBER: 210-0118; Package Type: SOD-323
J17 = CONN_DC2086: CONN.,HDR,SHROUDED,MALE,1x4,2mm,VERT,ST,THT; CLASS: IO; Inventory Qty: 5376; Manufacturer: HIROSE ELECTRIC; Manufacturer PN: DF3A-4P-2DSA; PART_NUMBER: 250-0491
J18 = CONN_7._FCI_12_POS_2MM: CONN.,HDR,SHROUDED,MALE,2x6,2mm,VERT,ST,THT; CLASS: IO; Inventory Qty: 12768; Manufacturer: AMPHENOL; Manufacturer PN: 98414-G06-12ULF; PART_NUMBER: 250-0433
J19 = PMBUS_CON14_0: CONN.,HDR,FEMALE,2x7,2mm,R/A THT; CLASS: IO; Inventory Qty: 10175; Manufacturer: SULLINS CONNECTOR SOLUTIONS; Manufacturer PN: NPPN072FJFN-RC; PART_NUMBER: 250-0461
J20 = PMBUS_CON14_2: CONN.,HDR,MALE,2x7,2mm,R/A THT; CLASS: IO; Inventory Qty: 11393; Manufacturer: MOLEX; Manufacturer PN: 0877601416; PART_NUMBER: 250-0462
R168 R169 = RES: RES.,4.99k OHMS,1%,1/10W,0603; CLASS: DISCRETE; FPLIST: CR0603N,CR0603L,CR0603M; Inventory Qty: 72747; Manufacturer: PANASONIC; Manufacturer PN: ERJ3EKF4991V; PART_NUMBER: 100-0121; Package Size: 0603; Rated Power: 1/10W; Temperature Coefficient: 100ppm/C; Tolerance: 1%
U2 = 24LC025-I_ST_TSSOP-8: IC, MEMORY,EEPROM,2Kb (256x8),TSSOP-8,400kHz; CLASS: IC; FPLIST: TSSOP-8N,TSSOP-8L,TSSOP-8M,MICROCHIP-TSSOP-8; Inventory Qty: 19510; Manufacturer: Microchip; PART_NUMBER: 380-0087; Package Size: TSSOP-8; Package Type: TSSOP-8

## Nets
3V3: E32.1 J18.5(LGKPWR) Q1.3(D) Q2.3(D) Q7.2(S) Q8.2(S) Q9.2(S) Q10.2(S) Q11.2(S) Q12.2(S) R115.1 R116.1 R117.1 R118.1 R155.1
GND: C25.1 C26.1 C27.1 C28.1 C29.2 C30.2 C44.1 C45.2 C46.2 C47.2 C48.2 C49.2 C50.2 C51.2 C52.2 C53.2 C54.2 C55.2 C56.2 C57.2 C58.2 C59.2 C60.2 C61.2 C62.2 C63.2 C64.2 COUT29.2 E40.1 E41.1 E42.1 E43.1 E45.1 E47.1 J11.2 J11.3 J11.4 J11.5 J12.2 J12.3 J12.4 J12.5 J13.2 J13.3 J13.4 J13.5 J14.2 J14.3 J14.4 J14.5 J15.2 J15.3 J15.4 J15.5 J16.2 J16.3 J16.4 J16.5 J17.2(GND) J18.3(GND) J18.10(GND) J19.11(GND) J19.12(GND) J20.11(GND) J20.12(GND) Q3.2(S) Q4.2(S) Q5.2(S) Q6.2(S) R108.2 R110.2 R111.2 R112.2 R113.2 R114.2 R119.2 R120.2 R121.2 R122.2 R123.2 R124.2 R125.2 R126.2 R127.2 R130.2 R131.2 R132.2 R178.1 SWR0.3 SWR1.3 SWR2.3 SWR3.3 U2.1(A0) U2.2(A1) U2.3(A2) U2.4(VSS) U2.7(WP) ; also on sheet 2
GND_SIGNAL: E39.1 ; also on sheet 2
SVIN_01: R105.1 ; also on sheet 2
SVIN_23: R106.1 ; also on sheet 2
VDD25_01: E15.1 ; also on sheet 2
VDD25_23: E16.1 ; also on sheet 2
VDD33_01: D11.1(C) E13.1 Q1.2(S) R135.2 R137.2 ; also on sheet 2
VDD33_23: D12.1(C) E14.1 Q2.2(S) R139.2 R141.2 ; also on sheet 2
VIN: R107.1 R109.1 R172.1 ; also on sheet 2
ALERTB: E36.1 J18.6(ALERTB) J19.3(ALERTB) J20.3(ALERTB) R147.2 R148.2
ALERTB_01: E30.1 Q7.1(G) R147.1 ; also on sheet 2
ALERTB_23: E31.1 Q8.1(G) R148.1 ; also on sheet 2
AUXP: C44.2 E33.1 J18.1(AUXP) J19.8(AUXP) J20.8(AUXP) R168.2 R169.2 U2.8(VCC)
AUXSCL: J18.11(AUXSCL) R168.1 U2.6(SCL)
AUXSDA: J18.12(AUXSDA) R169.1 U2.5(SDA)
COMP0a: R90.1 ; also on sheet 2
COMP0b: R93.1 ; also on sheet 2
COMP1a: R90.2 R91.1 ; also on sheet 2
COMP1b: R93.2 R94.1 ; also on sheet 2
COMP2a: R91.2 R92.1 ; also on sheet 2
COMP2b: R94.2 R95.1 ; also on sheet 2
COMP3a: R92.2 ; also on sheet 2
COMP3b: R95.2 ; also on sheet 2
FAULT0B: D13.2(A) E26.1 Q9.1(G) R99.1 R156.2 R164.1 ; also on sheet 2
FAULT1B: D14.2(A) E27.1 Q10.1(G) R99.2 R100.1 R157.2 R165.1 ; also on sheet 2
FAULT2B: D15.2(A) E28.1 Q11.1(G) R100.2 R101.1 R158.2 R166.1 ; also on sheet 2
FAULT3B: D16.2(A) E29.1 Q12.1(G) R101.2 R159.2 R167.1 ; also on sheet 2
FAULTB: J19.1(FAULTB) J20.1(FAULTB) R156.1 R157.1 R158.1 R159.1 R173.1 R174.1 R175.1 R176.1
INTVCC_01: E11.1 R105.2 ; also on sheet 2
INTVCC_23: E12.1 R106.2 ; also on sheet 2
PGOOD0: E22.1 Q3.1(G) R96.1 ; also on sheet 2
PGOOD1: E23.1 Q4.1(G) R96.2 R97.1 ; also on sheet 2
PGOOD2: E24.1 Q5.1(G) R97.2 R98.1 ; also on sheet 2
PGOOD3: E25.1 Q6.1(G) R98.2 ; also on sheet 2
RUN0: D13.1(C) E18.1 R102.1 R135.1 R136.2 R160.2 R165.2 R173.2 SWR0.1 SWR0.2 ; also on sheet 2
RUN1: D14.1(C) E19.1 R102.2 R103.1 R137.1 R138.2 R161.2 R164.2 R174.2 SWR1.1 SWR1.2 ; also on sheet 2
RUN2: D15.1(C) E20.1 R103.2 R104.1 R139.1 R140.2 R162.2 R167.2 R175.2 SWR2.1 SWR2.2 ; also on sheet 2
RUN3: D16.1(C) E21.1 R104.2 R141.1 R142.2 R163.2 R166.2 R176.2 SWR3.1 SWR3.2 ; also on sheet 2
SCL: E35.1 J17.3(SCL) J18.4(SCL) J19.6(SCL) J20.6(SCL) R145.2 R146.2
SCL_01: R145.1 ; also on sheet 2
SCL_23: R146.1 ; also on sheet 2
SDA: E34.1 J17.1(SDA) J18.2(SDA) J19.4(SDA) J20.4(SDA) R143.2 R144.2
SDA_01: R143.1 ; also on sheet 2
SDA_23: R144.1 ; also on sheet 2
SHARE_CLK: E37.1 R149.2 R150.2 R153.1
SHARE_CLK_01: R149.1 ; also on sheet 2
SHARE_CLK_23: R150.1 ; also on sheet 2
SYNC: E38.1 R151.2 R152.2 R154.1
SYNC_01: R151.1 ; also on sheet 2
SYNC_23: R152.1 ; also on sheet 2
VBIAS: E17.1 ; also on sheet 2
VOSNS0+: R84.1 R177.2 ; also on sheet 2
VOSNS0-: R87.1 R178.2 ; also on sheet 2
VOSNS1+: R84.2 R85.1 ; also on sheet 2
VOSNS1-: R87.2 R88.1 ; also on sheet 2
VOSNS2+: R85.2 R86.1 ; also on sheet 2
VOSNS2-: R88.2 R89.1 ; also on sheet 2
VOSNS3+: R86.2 ; also on sheet 2
VOSNS3-: R89.2 ; also on sheet 2
VOUT0: C46.1 C53.1 C54.1 C55.1 J11.1 R72.1 R73.1 R74.1 R75.1 R111.1 R128.2 ; also on sheet 2
VOUT1: C47.1 C56.1 C57.1 C58.1 COUT29.1 J12.1 R72.2 R73.2 R74.2 R75.2 R76.1 R77.1 R78.1 R79.1 R112.1 R129.2 R177.1 ; also on sheet 2
VOUT2: C29.1 C59.1 C60.1 C61.1 J15.1 R76.2 R77.2 R78.2 R79.2 R80.1 R81.1 R82.1 R83.1 R113.1 R133.2 ; also on sheet 2
VOUT3: C30.1 C62.1 C63.1 C64.1 J16.1 R80.2 R81.2 R82.2 R83.2 R114.1 R134.2 ; also on sheet 2
N20417880: D11.2(A) D12.2(A) J17.4(AUX3V4)
N20745285: Q1.1(G) R107.2 R108.1
N21610520: Q2.1(G) R109.2 R110.1
N21611299: C45.1 C49.1 C50.1 Q13.2(D) Q14.2(D) R128.1 R129.1
N21611453: E44.1 Q13.1(G) Q14.1(G) R125.1
N21611513: J13.1 Q13.3(S) Q14.3(S) R126.1 R127.1
N21613900: D3.2(ANODE) R117.2
N21613906: D1.2(ANODE) R115.2
N21613908: D2.2(ANODE) R116.2
N21613950: D1.1(CATHODE) Q3.3(D)
N21613952: D2.1(CATHODE) Q4.3(D)
N21613954: D3.1(CATHODE) Q5.3(D)
N21613956: D4.1(CATHODE) Q6.3(D)
N21614139: D5.2(ANODE) Q7.3(D)
N21614141: D7.2(ANODE) Q9.3(D)
N21614143: D8.2(ANODE) Q10.3(D)
N21614181: D5.1(CATHODE) R119.1
N21614183: D8.1(CATHODE) R122.1
N21615684: D9.2(ANODE) Q11.3(D)
N21615694: D9.1(CATHODE) R123.1
N21617020: D6.2(ANODE) Q8.3(D)
N21617030: D6.1(CATHODE) R120.1
N21617571: D10.2(ANODE) Q12.3(D)
N21617581: D10.1(CATHODE) R124.1
N21619088: D7.1(CATHODE) R121.1
N21636889: C48.1 C51.1 C52.1 Q15.2(D) Q16.2(D) R133.1 R134.1
N21636981: E46.1 Q15.1(G) Q16.1(G) R130.1
N21636997: J14.1 Q15.3(S) Q16.3(S) R131.1 R132.1
N21698479: J19.2(CTRL) J20.2(CTRL) R160.1 R161.1 R162.1 R163.1 R170.2 R171.2
N21698488: J19.5(SHARE_CLK) J20.5(SHARE_CLK) R153.2
N21698494: J19.7(RESETB) J20.7(RESETB)
N21698511: J19.9(UNUSED) J20.9(UNUSED) R154.2
N21698514: J19.10(UNUSED) J20.10(UNUSED) R155.2
N21698523: J19.13(12V) J19.14(12V) J20.13(12V) J20.14(12V) R172.2
N21709071: J18.9(OUTEN_1) R171.1
N21709268: J18.8(OUTEN_0) R170.1
N21727297: C25.2 R136.1
N21727299: C26.2 R138.1
N21727301: C27.2 R140.1
N21727303: C28.2 R142.1
N21783893: D4.2(ANODE) R118.2

Not connected (* = marked no-connect by the designer): J18 7(GPIO_1)*; SWR0 4 5 6; SWR1 4 5 6; SWR2 4 5 6; SWR3 4 5 6

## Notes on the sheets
sheet 3
- TEST POINTS
- OPTIONAL ZERO OHM JUMPERS FOR PARALLEL  OPERATION
- OPTIONAL SYSTEM 3V3 /100mA
- RUN0, RUN1, RUN2, RUN3  SWITCHES
- 2512
- 2512
- 2512
- 2512
- 2512
- 2512
- 2512
- 2512
- 2512
- 2512
- 2512
- 2512
- OPTIONAL LEDs INDICATION
- PGOOD0
- PGOOD1
- PGOOD2
- PGOOD3
- ALERTB_01
- ALERTB_23
- FAULT0B
- FAULT1B
- FAULT2B
- FAULT3B
- OPTIONAL DYNAMIC LOAD STEP CIRCUIT
- 4.5V<VIN <5.75V
- DYNAMIC LOAD STEP CIRCUIT FOR CHANNEL 0 or CHANNEL 1
- DYNAMIC LOAD STEP CIRCUIT FOR CHANNEL 2 or CHANNEL 3
- *SVIN_01, SVIN_23 are tied to VIN
- *RUNP is tied to GND
- OPTIONAL BLEEDER  LOADs
- 2512
- 2512
- 2512
- 2512
sheet 4
- OPTIONAL EEPROM IDENTIFICATION, DC1613A CONNECTOR and BOARD TO BOARD PMBUS CONNECTORS (DEMO BOARD ONLY)
- TO DC2086A
- FCI 98414-G06-12ULF
- SULLINS NPPN072FJFN-RC
- TO DC1613A
- MOLEX 87760-1416
